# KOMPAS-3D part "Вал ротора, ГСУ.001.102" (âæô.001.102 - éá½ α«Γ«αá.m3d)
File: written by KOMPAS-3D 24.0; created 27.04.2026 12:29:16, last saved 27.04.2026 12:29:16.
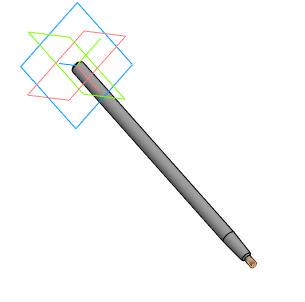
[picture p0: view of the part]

Document properties: Автор: User7; Полное имя файла: C:\Users\User7\Desktop\олимп\ГСУ.001.102 - Вал ротора.m3d

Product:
- Part/product: Вал ротора  | designation ГСУ.001.102
    Масса: 0.060205

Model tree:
1. Эскиз:1
2. Элемент вращения:1
     Угол 1 = 360
3. Условное изображение резьбы:1  (with: Грань.Элемент вращения:1, Ребро.Элемент вращения:1)  (labels: M4; cil0_24705-2004 coarse)
     Длина резьбы = 4; Шаг резьбы = 0.7; Номинальный диаметр резьбы = 4
4. Подгонка:1  (with: Грань.Элемент вращения:1)
5. Скругление:1  (with: Ребро.Элемент вращения:1)
     Радиус = 1
6. Фаска:1  (with: Ребро.Элемент вращения:1)
     Угол = 45; Длина 1 = 1; Длина 2 = 1

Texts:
  ГСУ.001.102
  Линейный размер с обрывом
